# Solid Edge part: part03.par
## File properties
Author: Administrator
Template: normal.par
Last saved by: CADCIM
Revision: 12
Application: Solid Edge
Accuracy: 0.99
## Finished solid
Body 1: solid body, 54 faces, 136 edges, 72 vertices.
  Faces by surface: cylinder 40, plane 14
  Edges by curve: circle 74, line 50, ellipse 12
Bounding box of the edges (mm): 320.500 x 112.000 x 70.000, from (-118.4884, -56, -35) to (202.0116, 56, 35).
Cylindrical faces by radius (mm): R5 x8, R6 x2, R12 x1, R13 x8, R17.5 x1, R26 x1, R31.5 x3, R35 x2, R72.03 x8, R78 x4, R207.0766 x1, R207.2725 x1
Planar faces by outward normal: +y 1, +z 4, -y 1, -z 4, oblique 4
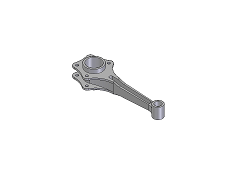
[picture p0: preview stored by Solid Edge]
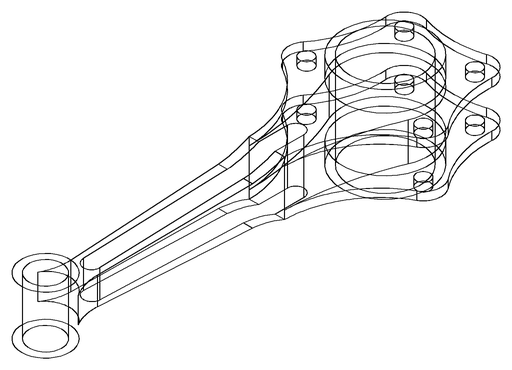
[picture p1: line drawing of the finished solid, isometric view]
